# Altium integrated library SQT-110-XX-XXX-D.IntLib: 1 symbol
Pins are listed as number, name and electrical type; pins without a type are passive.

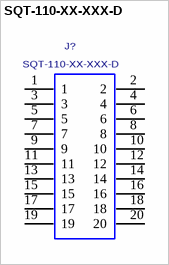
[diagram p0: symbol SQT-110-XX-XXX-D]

## SQT-110-XX-XXX-D
designator J?
2MM SOCKET STRIP ASSEMBLY, 20 PINS.; MANUFACTURER: SAMTEC
footprint SQT-110-XX-XXX-D
pins: 1, 2, 3, 4, 5, 6, 7, 8, 9, 10, 11, 12, 13, 14, 15, 16, 17, 18, 19, 20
